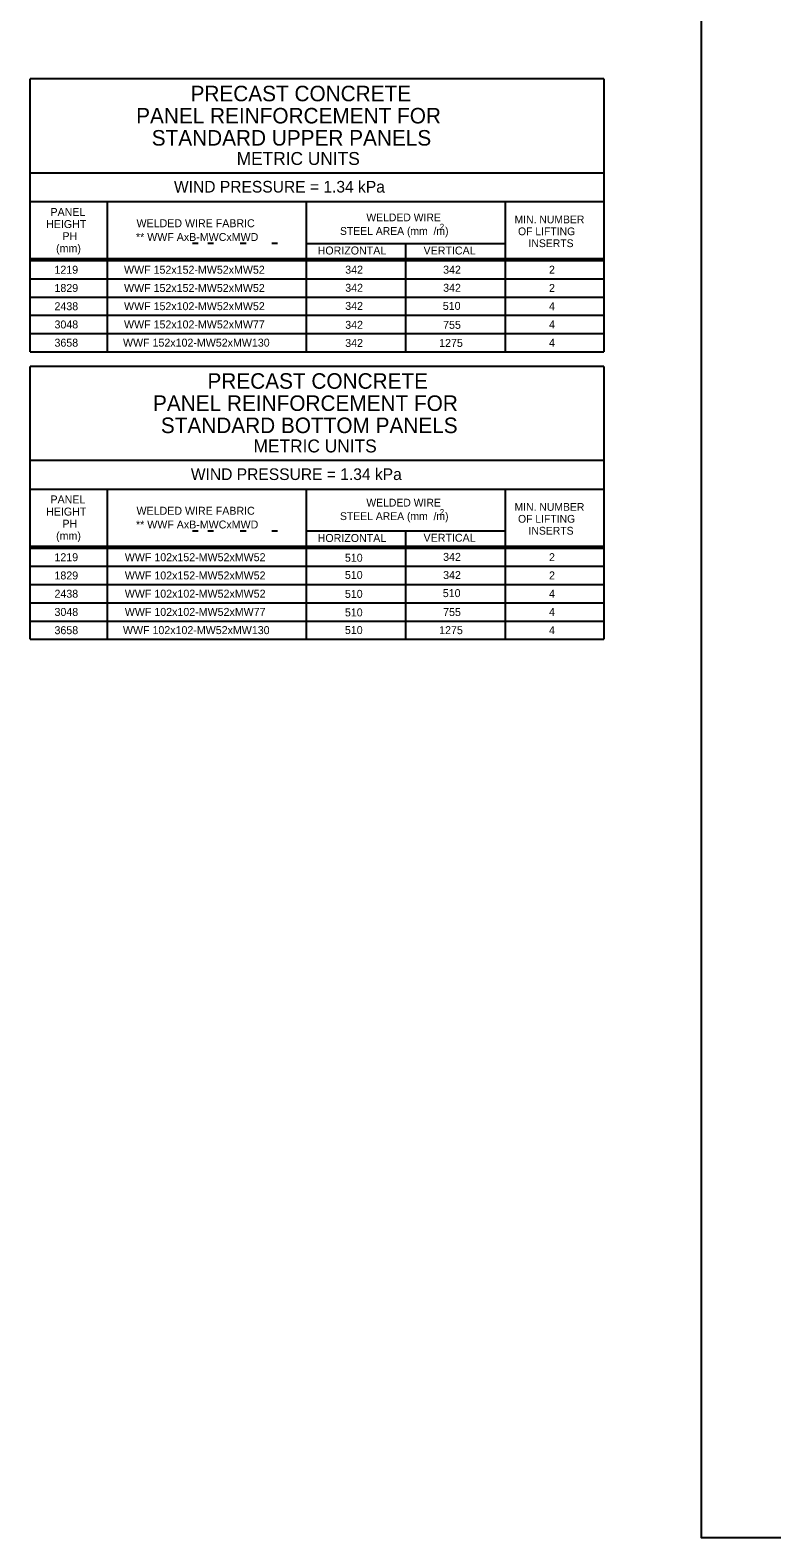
# Model space of a CAD drawing. Extents: x 3385 to 6532, y -616 to 1166.
# Drawn here: x 4343 to 4629, y -616 to -34 of the extents above; entities that cross this region are included whole.
import ezdxf

# ---------------------------------------------------------------- set-up
doc = ezdxf.new("R2010")
doc.units = 0
doc.layers.add('1', color=7, linetype='Continuous')
doc.layers.add('PLT-BNDY', color=7, linetype='Continuous')

msp = doc.modelspace()

# ---------------------------------------------------------------- linework, layer by layer
at = {"layer": '1'}
for p, q in [((4564.54, -52.92), (4343.1, -52.92)), ((4343.1, -158.29), (4343.1, -52.92)), ((4564.54, -52.92), (4564.54, -158.29)), ((4564.54, -89.34), (4343.1, -89.34)), ((4343.1, -100.32), (4564.54, -100.32)), ((4372.84, -100.32), (4372.84, -158.29)), ((4449.64, -100.32), (4449.64, -158.29)), ((4526.44, -100.32), (4526.44, -158.29)), ((4405.72, -116.37), (4407.95, -116.37)), ((4411.72, -116.37), (4413.95, -116.37)), ((4424.21, -116.37), (4426.44, -116.37)), ((4436.39, -116.37), (4438.62, -116.37)), ((4449.64, -116.45), (4526.44, -116.45)), ((4488.04, -116.45), (4488.04, -158.29)), ((4343.1, -122.34), (4564.54, -122.34)), ((4343.1, -123.09), (4564.54, -123.09)), ((4343.1, -130.13), (4564.54, -130.13)), ((4343.1, -137.17), (4564.54, -137.17)), ((4343.1, -144.21), (4564.54, -144.21)), ((4343.1, -151.25), (4564.54, -151.25)), ((4343.1, -158.29), (4564.54, -158.29)), ((4564.54, -163.93), (4343.1, -163.93)), ((4343.1, -269.31), (4343.1, -163.93)), ((4564.54, -163.93), (4564.54, -269.31)), ((4564.54, -200.35), (4343.1, -200.35)), ((4343.1, -211.34), (4564.54, -211.34)), ((4372.84, -211.34), (4372.84, -269.31)), ((4449.64, -211.34), (4449.64, -269.31)), ((4526.44, -211.34), (4526.44, -269.31)), ((4405.72, -227.39), (4407.95, -227.39)), ((4411.72, -227.39), (4413.95, -227.39)), ((4424.21, -227.39), (4426.44, -227.39)), ((4436.39, -227.39), (4438.62, -227.39)), ((4449.64, -227.47), (4526.44, -227.47)), ((4488.04, -227.47), (4488.04, -269.31)), ((4343.1, -233.35), (4564.54, -233.35)), ((4343.1, -234.1), (4564.54, -234.1)), ((4343.1, -241.15), (4564.54, -241.15)), ((4343.1, -248.19), (4564.54, -248.19)), ((4343.1, -255.23), (4564.54, -255.23)), ((4343.1, -262.27), (4564.54, -262.27)), ((4343.1, -269.31), (4564.54, -269.31))]:
    msp.add_line(p, q, dxfattribs=at)
at = {"layer": 'PLT-BNDY'}
msp.add_lwpolyline([(4602.34, -22.31), (5443.34, -22.31), (5443.34, -616.31), (4602.34, -616.31)], close=True, dxfattribs=at)

# ---------------------------------------------------------------- texts
at = {"layer": '1'}
for s, height, p in [('PRECAST CONCRETE', 6.0001, (4405.03, -61.58)), ('PANEL REINFORCEMENT FOR', 6.0001, (4384.02, -70.14)), ('STANDARD UPPER PANELS', 6.0001, (4390.04, -78.69)), ('METRIC UNITS', 5.0001, (4422.83, -86.17)), ('WIND PRESSURE = 1.34 kPa', 4.5001, (4398.62, -96.82)), ('PANEL', 3.072, (4350.95, -105.86)), ('HEIGHT', 3.072, (4349.27, -110.53)), ('WELDED WIRE FABRIC', 3.072, (4384.17, -110.21)), ('STEEL AREA (mm  /m)', 3, (4462.73, -113.16)), ('WELDED WIRE', 3, (4472.91, -107.92)), ('2', 2.3, (4501.23, -111.19)), ('MIN. NUMBER', 3, (4530.11, -108.7)), ('OF LIFTING', 3, (4531.46, -113.3)), ('PH', 3.072, (4355.56, -115.2)), ('** WWF AxB-MWCxMWD', 3.072, (4383.96, -115.52)), ('INSERTS', 3, (4535.52, -117.9)), ('(mm)', 3.072, (4353.12, -119.88)), ('HORIZONTAL', 3.072, (4454.11, -120.74)), ('VERTICAL', 3.072, (4494.99, -120.74)), ('1219', 3.072, (4352.48, -128.16)), ('WWF 152x152-MW52xMW52', 3.072, (4379.35, -128.16)), ('342', 3.072, (4464.75, -128.15)), ('342', 3.072, (4502.55, -128.15)), ('2', 3.07, (4543.42, -128.15)), ('1829', 3.072, (4352.49, -135.21)), ('WWF 152x152-MW52xMW52', 3.072, (4379.35, -135.2)), ('342', 3.072, (4464.75, -135.14)), ('342', 3.072, (4502.55, -135.14)), ('2', 3.07, (4543.43, -135.2)), ('2438', 3.072, (4352.5, -142.26)), ('WWF 152x102-MW52xMW52', 3.072, (4379.35, -142.24)), ('342', 3.072, (4464.75, -142.13)), ('510', 3.072, (4502.42, -142.13)), ('4', 3.07, (4543.43, -142.25)), ('3048', 3.072, (4352.5, -149.29)), ('WWF 152x102-MW52xMW77', 3.072, (4379.35, -149.28)), ('342', 3.072, (4464.75, -149.44)), ('755', 3.072, (4502.55, -149.44)), ('4', 3.07, (4543.43, -149.29)), ('3658', 3.072, (4352.5, -156.34)), ('WWF 152x102-MW52xMW130', 3.072, (4378.95, -156.32)), ('342', 3.072, (4464.75, -156.43)), ('1275', 3.072, (4501.01, -156.43)), ('4', 3.07, (4543.43, -156.33)), ('PRECAST CONCRETE', 6.0001, (4411.56, -172.59)), ('PANEL REINFORCEMENT FOR', 6.0001, (4390.54, -181.15)), ('STANDARD BOTTOM PANELS', 6.0001, (4393.57, -189.71)), ('METRIC UNITS', 5.0001, (4429.35, -197.18)), ('WIND PRESSURE = 1.34 kPa', 4.5001, (4405.15, -207.83)), ('PANEL', 3.072, (4350.95, -216.87)), ('WELDED WIRE', 3, (4472.91, -218.06)), ('HEIGHT', 3.072, (4349.27, -221.55)), ('WELDED WIRE FABRIC', 3.072, (4384.17, -221.23)), ('STEEL AREA (mm  /m)', 3, (4462.73, -223.29)), ('2', 2.3, (4501.23, -221.33)), ('MIN. NUMBER', 3, (4530.11, -219.71)), ('PH', 3.072, (4355.56, -226.22)), ('** WWF AxB-MWCxMWD', 3.072, (4383.96, -226.54)), ('OF LIFTING', 3, (4531.46, -224.31)), ('INSERTS', 3, (4535.52, -228.91)), ('(mm)', 3.072, (4353.12, -230.89)), ('HORIZONTAL', 3.072, (4454.11, -231.75)), ('VERTICAL', 3.072, (4494.99, -231.66)), ('1219', 3.072, (4352.48, -239.17)), ('WWF 102x152-MW52xMW52', 3.072, (4379.65, -239.17)), ('510', 3.072, (4464.62, -239.37)), ('342', 3.072, (4502.55, -239.05)), ('2', 3.07, (4543.42, -239.16)), ('1829', 3.072, (4352.49, -246.22)), ('WWF 102x152-MW52xMW52', 3.072, (4379.65, -246.21)), ('510', 3.072, (4464.62, -246.03)), ('342', 3.072, (4502.55, -246.05)), ('2', 3.07, (4543.43, -246.21)), ('2438', 3.072, (4352.5, -253.28)), ('WWF 102x102-MW52xMW52', 3.072, (4379.65, -253.25)), ('510', 3.072, (4464.62, -253.33)), ('510', 3.072, (4502.42, -253.04)), ('4', 3.07, (4543.43, -253.26)), ('3048', 3.072, (4352.5, -260.31)), ('WWF 102x102-MW52xMW77', 3.072, (4379.65, -260.29)), ('510', 3.072, (4464.62, -260.48)), ('755', 3.072, (4502.55, -260.35)), ('4', 3.07, (4543.43, -260.31)), ('3658', 3.072, (4352.5, -267.36)), ('WWF 102x102-MW52xMW130', 3.072, (4378.93, -267.33)), ('510', 3.072, (4464.62, -267.3)), ('1275', 3.072, (4501.01, -267.34)), ('4', 3.07, (4543.43, -267.35))]:
    msp.add_text(s, height=height, dxfattribs=at).set_placement(p)

doc.saveas('drawing.dxf')
